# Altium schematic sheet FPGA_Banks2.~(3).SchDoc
size A4
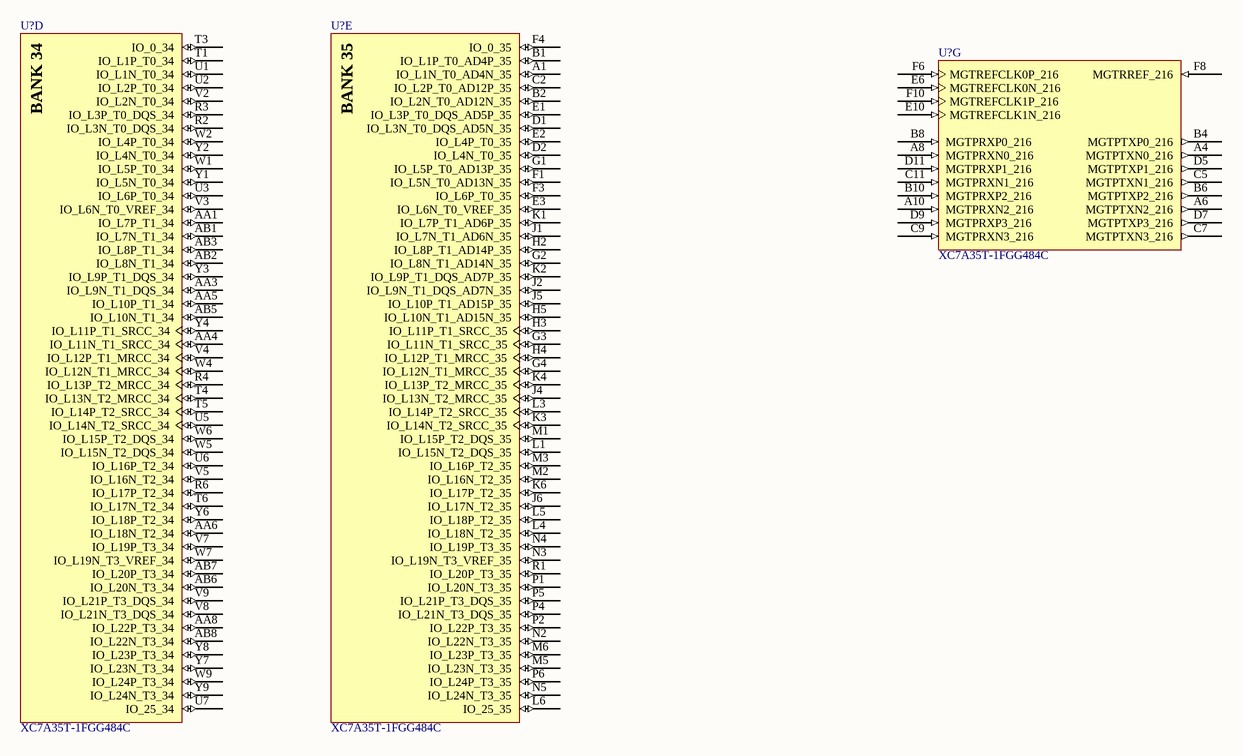
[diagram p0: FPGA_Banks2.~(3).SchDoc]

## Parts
(Parts that share a designator on the sheet are numbered #1, #2 ... from top to bottom, then left to right.)
U?#1  XC7A35T-1FGG484C  [FGG484]  (part D of 12)
U?#2  XC7A35T-1FGG484C  [FGG484]  (part E of 12)
U?#3  XC7A35T-1FGG484C  [FGG484]  (part G of 12)

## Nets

Not connected (* = marked no-connect by the designer): U?#1 AA1(IO_L7P_T1_34) AA3(IO_L9N_T1_DQS_34) AA4(IO_L11N_T1_SRCC_34) AA5(IO_L10P_T1_34) AA6(IO_L18N_T2_34) AA8(IO_L22P_T3_34) AB1(IO_L7N_T1_34) AB2(IO_L8N_T1_34) AB3(IO_L8P_T1_34) AB5(IO_L10N_T1_34) AB6(IO_L20N_T3_34) AB7(IO_L20P_T3_34) AB8(IO_L22N_T3_34) R2(IO_L3N_T0_DQS_34) R3(IO_L3P_T0_DQS_34) R4(IO_L13P_T2_MRCC_34) R6(IO_L17P_T2_34) T1(IO_L1P_T0_34) T3(IO_0_34) T4(IO_L13N_T2_MRCC_34) T5(IO_L14P_T2_SRCC_34) T6(IO_L17N_T2_34) U1(IO_L1N_T0_34) U2(IO_L2P_T0_34) U3(IO_L6P_T0_34) U5(IO_L14N_T2_SRCC_34) U6(IO_L16P_T2_34) U7(IO_25_34) V2(IO_L2N_T0_34) V3(IO_L6N_T0_VREF_34) V4(IO_L12P_T1_MRCC_34) V5(IO_L16N_T2_34) V7(IO_L19P_T3_34) V8(IO_L21N_T3_DQS_34) V9(IO_L21P_T3_DQS_34) W1(IO_L5P_T0_34) W2(IO_L4P_T0_34) W4(IO_L12N_T1_MRCC_34) W5(IO_L15N_T2_DQS_34) W6(IO_L15P_T2_DQS_34) W7(IO_L19N_T3_VREF_34) W9(IO_L24P_T3_34) Y1(IO_L5N_T0_34) Y2(IO_L4N_T0_34) Y3(IO_L9P_T1_DQS_34) Y4(IO_L11P_T1_SRCC_34) Y6(IO_L18P_T2_34) Y7(IO_L23N_T3_34) Y8(IO_L23P_T3_34) Y9(IO_L24N_T3_34); U?#2 A1(IO_L1N_T0_AD4N_35) B1(IO_L1P_T0_AD4P_35) B2(IO_L2N_T0_AD12N_35) C2(IO_L2P_T0_AD12P_35) D1(IO_L3N_T0_DQS_AD5N_35) D2(IO_L4N_T0_35) E1(IO_L3P_T0_DQS_AD5P_35) E2(IO_L4P_T0_35) E3(IO_L6N_T0_VREF_35) F1(IO_L5N_T0_AD13N_35) F3(IO_L6P_T0_35) F4(IO_0_35) G1(IO_L5P_T0_AD13P_35) G2(IO_L8N_T1_AD14N_35) G3(IO_L11N_T1_SRCC_35) G4(IO_L12N_T1_MRCC_35) H2(IO_L8P_T1_AD14P_35) H3(IO_L11P_T1_SRCC_35) H4(IO_L12P_T1_MRCC_35) H5(IO_L10N_T1_AD15N_35) J1(IO_L7N_T1_AD6N_35) J2(IO_L9N_T1_DQS_AD7N_35) J4(IO_L13N_T2_MRCC_35) J5(IO_L10P_T1_AD15P_35) J6(IO_L17N_T2_35) K1(IO_L7P_T1_AD6P_35) K2(IO_L9P_T1_DQS_AD7P_35) K3(IO_L14N_T2_SRCC_35) K4(IO_L13P_T2_MRCC_35) K6(IO_L17P_T2_35) L1(IO_L15N_T2_DQS_35) L3(IO_L14P_T2_SRCC_35) L4(IO_L18N_T2_35) L5(IO_L18P_T2_35) L6(IO_25_35) M1(IO_L15P_T2_DQS_35) M2(IO_L16N_T2_35) M3(IO_L16P_T2_35) M5(IO_L23N_T3_35) M6(IO_L23P_T3_35) N2(IO_L22N_T3_35) N3(IO_L19N_T3_VREF_35) N4(IO_L19P_T3_35) N5(IO_L24N_T3_35) P1(IO_L20N_T3_35) P2(IO_L22P_T3_35) P4(IO_L21N_T3_DQS_35) P5(IO_L21P_T3_DQS_35) P6(IO_L24P_T3_35) R1(IO_L20P_T3_35); U?#3 A4(MGTPTXN0_216) A6(MGTPTXN2_216) A8(MGTPRXN0_216) A10(MGTPRXN2_216) B4(MGTPTXP0_216) B6(MGTPTXP2_216) B8(MGTPRXP0_216) B10(MGTPRXP2_216) C5(MGTPTXN1_216) C7(MGTPTXN3_216) C9(MGTPRXN3_216) C11(MGTPRXN1_216) D5(MGTPTXP1_216) D7(MGTPTXP3_216) D9(MGTPRXP3_216) D11(MGTPRXP1_216) E6(MGTREFCLK0N_216) E10(MGTREFCLK1N_216) F6(MGTREFCLK0P_216) F8(MGTRREF_216) F10(MGTREFCLK1P_216)

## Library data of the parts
U?#1-U?#3 = XC7A35T-1FGG484C: Artix-7 FPGA, 250 User I/Os, 4 GTP, 484-Ball BGA, Speed Grade 1, Commercial Grade, Pb-Free; Manufacturer: Xilinx; Total Block RAM: 1800 Kb; GTP: 4; Clock Mgmt Tiles (CMTs): 5; Logic Cells: 33280; Available User I/O: 250; Speed Grades: 1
